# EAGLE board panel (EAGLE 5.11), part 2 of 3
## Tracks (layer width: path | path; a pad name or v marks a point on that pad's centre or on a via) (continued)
3.3V1  (via drill 0.4, 0.5) (continued)
  Top 0.406: SPEKTRUM_TX.3 150.02,10.82 151.45,12.25 151.45,14.71 v149.71,16.45
  Bottom 0.406: v159.07,21.26 | v159.07,21.26 | v159.07,21.26 | C96.1 145.26,24.33 IC31.5 C95.1 148.75,23.15 | 148.75,23.15 149.94,23.15 152.22,23.15 v152.64,22.72 154.23,21.14 157.25,21.14 158.79,21.14 v159.07,21.26 | v149.71,16.45 149.71,20.03 148.67,21.06 148.67,23.07 148.75,23.15 | v165.58,15.5 165.58,22.09 164.15,23.52 160.82,23.52 159.87,22.57 159.07,21.77 v159.07,21.26
3_3
  Top 0.254: JP4.3 86.96,35.55 86.96,28.06 87.52,27.5 87.81,27.5 89.06,26.25 IC12.48
5V
  Bottom 0.406: JP6.2 126.71,37.27 C79.1 126.69,39.04 | 126.69,39.04 IC27.5 | IC27.8 126.69,42.85 126.69,39.04
7.4V
  Bottom 0.406: 165.29,10.98 C88.1 163.52,10.95 163.44,10.95 163.44,11.21 | IC30.8 159.71,13.3 159.71,15.34 163.44,15.34 IC30.5 163.44,11.21 | VCC.1 161.37,6.61 161.77,7.01 161.77,10.42 162.56,11.21 163.44,11.21
!RE  (via drill 0.4)
  Top 0.406: 176.92,87.09 IC1.9 175.42,87.09 v175.01,87.5 | IC2.3 IC2.2 168.31,79.49 168.31,81.8 v168.71,82.2
  Bottom 0.406: v168.71,82.2 169.71,82.2 v175.01,87.5
!RE2
  Top 0.406: IC15.9 15.21,98.7 13.41,96.9 12.01,96.9 9.51,94.5 9.51,94.4 8.98,93.87 IC13.2 IC13.3
!RE3
  Top 0.305: OK8.6 31.75,22.24
  Top 0.406: 31.75,22.24 31.31,21.8 20.01,21.8 19.81,21.6 17.51,21.6 17.05,21.14 IC20.3 IC20.2
!RST  (via drill 0.4)
  Top 0.305: IC1.29 169.61,89.5 169.91,89.8 v170.31,89.8 | ISP.5 174.03,97.3 169.71,97.3 168.03,98.98 R1.1
  Bottom 0.305: v170.31,89.8 172.81,89.8 173.31,89.3 174.21,89.3 176.81,91.9 176.81,97.93 ISP.5
!RST1  (via drill 0.4)
  Top 0.305: IC15.29 17.61,106.01 17.91,105.7 v18.71,105.7 | v22.11,106.9 23.61,106.9 26.31,104.2 26.31,101.28 ISP1.5 27.79,99.88 29.01,101.1 31.61,101.1 32.63,102.12 R38.1
  Bottom 0.305: v18.71,105.7 22.11,105.7 v22.11,106.9
+3V1  (via drill 0.4)
  Top 0.254: 91.04,22 91.04,20.93 87.53,20.93 IC12.8 85.71,20.95 85.71,20.9 85.81,20.9 C40.2 | v90.41,21.9 90.51,22 91.04,22 | R30.2 85.41,25.05 v85.41,26.2 | R31.1 97.46,32.6 v100.21,32.6 | R32.2 104.56,23.55 103.91,24.2 v102.81,24.2 | 91.04,22 91.71,22.67 91.71,24.3 91.04,24.97 91.06,24.99 IC12.44 91.06,27.75 C41.2
  Top 0.406: JP4.9 101.86,35.41 C44.1 101.76,32.9 101.56,32.9 IC11.5 100.41,31.2 C43.1 100.31,32.5 v100.21,32.6
  Bottom 0.254: v102.81,24.2 102.81,25.2 100.81,27.2 100.81,32 v100.21,32.6
  Bottom 0.406: 87.01,26.1 88.31,24.8 88.31,24.2 89.61,22.9 90.31,22.9 90.41,22.8 v90.41,21.9 | 87.01,26.1 86.91,26.2 v85.41,26.2 | v100.21,32.6 91.51,32.6 87.81,28.9 87.81,26.9 87.01,26.1
+3V2  (via drill 0.4)
  Top 0.254: L5.P$1 L1A1.P$1
  Top 0.305: IC16.1 28.91,91.2 | v36.81,85.2 R43.2 | 28.91,91.8 v29.71,91.8
  Top 0.61: 28.91,90.5 28.91,91.2 28.91,91.8 28.91,94.3 L5.P$1
  Top 1.93: L5.P$1 28.76,96.05 30.01,97.3 C51.1 32.81,97.3 33.41,97.9 33.41,100.3 36.61,103.5 36.61,116.2 +5V1.MP
  Bottom 0.305: v36.81,85.2 35.61,86.4 35.61,88.5 33.11,91 30.61,91 29.81,91.8 v29.71,91.8
+5V  (via drill 0.4)
  Top 0.305: R1.2 168.05,101.55 ISP.2
  Top 0.406: 173.31,91.9 172.14,90.73 IC1.4 | 173.31,91.9 174.54,93.13 IC1.18 174.54,95.97 174.36,96.15 C3.1 | 173.31,91.9 173.74,91.47 v173.74,90.6 IC1.6 173.74,83.99 C2.1 172.6,82.09 172.21,81.7 171.41,81.7 170.91,81.2 170.91,75.4 | C12.2 177.36,77.4 IC4.1 175.92,76.01 175.31,75.4 170.91,75.4 | C1.1 169.55,71.09 IC2.8 169.55,74.94 170.01,75.4 170.91,75.4
  Bottom 0.406: v173.74,90.6 173.74,92.67 172.11,94.3 171.81,94.3 168.81,97.3 168.81,99.71 ISP.2
+5V1
  Bottom 0.406: IC29.8 C91.1 169.05,12.33 171.14,12.33 171.61,12.8 172.8,12.8 | IC29.8 | 172.8,12.8 IC29.5 | 172.8,12.8 | 172.8,12.8 175.74,12.8 176.46,12.09 176.46,9.31 175.82,8.67 173.92,8.67 SBUS.2 169.79,8.59 5V.1 | IC31.3 143.36,21.54 143.67,21.85 145.18,21.85 145.26,21.77 IC31.1 145.77,20.55 146.05,20.26 146.05,18.94 C94.1 146.13,18.86 146.13,17.8 147.96,15.9 148.83,15.02 | 155.02,16.93 155.26,17.17 156.14,18.04 156.65,18.56 C90.+ 158.81,18.76 IC30.1 IC30.2 160.9,19.71 160.5,20.1 160.5,21.85 160.9,22.25 C89.1 | 155.02,16.93 153.99,15.9 153.12,15.02 149.15,15.02 | 148.83,15.02 149.15,15.02 | 148.83,15.02 149.15,15.02 | 148.83,15.02 149.15,15.02 | IC29.8 166.47,14.73 166.06,14.31 165.18,14.31 164.79,14.71 164.47,15.02 164.47,16.06 164.23,16.29 163.68,16.29 158.36,16.29 155.66,16.29 155.02,16.93
+5V2  (via drill 0.4)
  Top 0.254: v100.91,25.9 100.91,28.6
  Top 0.406: 103.46,29.9 IC11.3 | 103.46,29.9 101.56,29.9 IC11.1 100.91,28.6 100.41,28.6 C42.1 | JP4.10 104.64,30.13 104.41,29.9 103.46,29.9
  Bottom 0.254: v100.91,25.9 100.91,25.8 99.91,24.8 99.31,24.8 98.81,24.3 U$1.VBUS
+5V3  (via drill 0.4, 0.6)
  Top 0.305: R38.2 31.84,104.96 ISP1.2
  Top 0.406: C47.1 10.75,103.78 10.75,103.22 12.09,101.87 IC15.6 v17.71,101.87 19.59,101.87 20.01,102.3 | 20.01,102.3 18.84,103.47 IC15.4 | 20.01,102.3 21.24,101.07 IC15.18 24.09,101.07 24.26,101.25 C49.1 | C63.2 13.91,85.2 IC17.1 v11.81,83.1 | IC13.8 14.47,95.14 C48.1 14.53,96.22 15.11,96.8 v16.21,96.8
  Bottom 0.406: ISP1.2 28.42,106.8 24.81,106.8 22.41,104.4 22.41,103.5 20.79,101.87 v17.71,101.87 16.21,100.37 v16.21,96.8 16.21,94 12.81,90.6 12.81,85.9 11.81,84.9 v11.81,83.1
+5V4  (via drill 0.4)
  Top 0.305: OK7.8 93.56,48.45 94.11,49 C57.2 96.01,49.8 96.01,52.1 | 103.11,52.5 102.99,52.63 IC14.4 97.74,52.63 97.21,52.1 96.01,52.1 | 96.01,52.1 93.69,52.1 OK6.2
  Top 0.35: IC14.20 104.59,49.38 103.12,47.91 103.11,47.92 103.11,52.5 103.11,54.8 | R45.2 R46.2 116.73,55.08 116.11,55.7 104.01,55.7 103.11,54.8 | 103.11,54.8 103.12,54.79 | L6.2 105.07,43.35 | 98.46,44.7 R47.1
  Top 0.406: 105.14,43.27 L6.2 104.41,43.17 | 104.41,43.17 104.36,43.17 C54.1 | 103.12,47.91 103.12,45.09 103.81,44.4 103.81,43.3 | 103.81,43.3 103.81,43.2 104.38,43.2 104.41,43.17 | 103.81,43.3 102.66,43.3 C56.+ 100.25,42.36 v99.51,43.1 99.51,43.65 98.46,44.7
  Bottom 0.35: 93.71,41.8 94.61,40.9 97.31,40.9 v99.51,43.1
+5V5
  Top 0.406: 30.01,26.8 30.01,27.1 | 6.71,19.2 IC18.1 6.71,20.8 | 28.61,25.5 C72.1 | 36.56,25.6 36.58,25.59 | 14.51,23.3 14.41,23.2 14.11,22.9
  Top 0.61: OK4.8 OK4.7 36.58,25.59 | OK8.8 OK8.7 30.48,24.54 30.01,25 30.01,25.5 | 30.01,27.1 29.31,27.7 21.81,27.7 arc90 R63.1 20.81,27.6 20.31,27.1 20.31,24.5 19.01,23.2 14.41,23.2 | 30.01,25.5 30.01,26.8 33.01,26.8 C71.1 36.56,25.6 | 30.01,25.5 28.61,25.5
  Top 0.813: 14.51,23.3 IC20.8 | 14.11,22.9 C73.1 7.41,22.9 6.71,22.2 6.71,20.8 C65.2
+5V6  (via drill 0.4)
  Top 0.305: 126.11,15.3 126.11,14.75 126.38,14.48 IC32.6 131.18,14.48 v132.06,15.1 | 126.11,15.3 126.11,15.8 126.39,16.08 IC32.4 | C97.2 126.11,15.3 | R89.2 v128.81,23.1 129.14,23.38 R90.1 R93.1 | R92.1 R91.1 141.16,23.39 141.16,22.55 140.76,22.15 v139.76,22.15 | SG4.- 139.59,11.91 L15.1 139.62,13.7 C102.2
  Bottom 0.305: 139.46,7.3 134.71,7.3 133.39,8.58 132.06,9.9 v132.06,15.1 132.06,19.2 129.96,21.3 129.96,21.95 129.41,22.5 | 139.58,7.3 ISP2.2 | 139.58,7.3 139.61,7.22 | IC33.1 124.11,21.03 C101.2 124.11,23.5 125.11,24.5 127.41,24.5 v128.81,23.1 129.41,22.5 | 129.41,22.5 129.81,22.9 132.66,22.9 133.36,22.2 139.71,22.2 v139.76,22.15 | 139.46,7.3 139.58,7.3 | 139.46,7.3 139.46,10.44 SG4.-
+12V  (via drill 0.4, 1)
  Top 0.406: IC6.7 159.09,60.33 158.26,61.15 Q8.2 | IC7.7 159.29,75.12 158.26,76.15 Q9.2 | IC8.7 158.99,91.73 157.96,92.75 Q10.2 | IC3.7 158.39,107.62 157.96,108.05 Q7.2 | R17.2 161.51,95.5 v160.61,96.4 | R14.2 161.71,78.6 v160.61,79.7 | v160.61,63.5 R11.2 | IC4.8 C13.2 v177.51,71
  Top 0.61: R8.2 159.31,112 159.11,112
  Top 1.27: C8.1 v160.61,63.5 Q8.2 | C10.1 160.61,81.9 v160.61,79.7 158.36,79.7 Q9.2 | C14.1 v160.61,96.4 158.06,96.4 Q10.2 | 160.31,112.9 C6.1 | 160.31,112.9 159.41,112 159.11,112 Q7.2 | 160.31,112.9 159.91,113.3 v159.81,113.3
  Top 1.778: X2.4 X2.5 | X1.5 X1.4
  Bottom 0.406: v177.51,71 175.66,72.85 175.66,74.05
  Bottom 1.27: v159.81,113.3 162.86,110.15 162.86,109.35
  Bottom 1.93: v160.61,63.5 v160.61,79.7 v160.61,96.4 160.61,107.1 162.86,109.35 164.51,111 171.42,111
  Bottom 2.54: X2.4 171.41,69.8 175.66,74.05 179.01,77.4 179.01,111 171.42,111 X1.5
+12V1  (via drill 0.6)
  Top 0.3: IC16.4 27.81,88.8 27.81,88.5
  Top 0.406: v10.71,75.4 10.41,75.4 5.61,80.2 5.61,84.2 IC17.8 4.22,85.2 C62.2
  Top 0.813: 27.81,88.5 27.81,87.5 28.91,86.4 C60.1
  Top 1.016: 29.11,76.09 29.21,76.2 31.01,78 31.01,80.1 28.91,82.2 C60.1 C59.1 | C61.1 22.99,74.83 X11.4
  Top 1.27: X11.5 29.21,76.2
  Top 1.778: X13.5 X13.4
  Top 1.93: X11.5 25.91,74.8 X11.5
  Top 2.184: X13.4 X11.4
  Bottom 0.406: v10.71,75.4 11.03,75.08 X13.5
  Bottom 1.778: X11.4 X11.5 | X13.5 X13.4
+12V2  (via drill 0.4)
  Top 0.305: v123.16,19.4 123.16,22.05 125.76,24.65 v128.81,24.65
  Bottom 0.305: v123.16,19.4 124.25,18.32 IC33.8 124.22,15.67 C100.2 124.21,12 123.8,11.59 SV2.4 | v128.81,24.65 128.96,24.5 140.26,24.5 140.96,23.8 140.96,21.35 140.91,21.35 140.66,21.1 138.55,21.1 R95.2
+18V  (via drill 0.6)
  Top 0.305: v138.17,108.54 138.96,109.18 139.11,109.33 IC21.7 139.13,111.71 R66.2 | R69.2 139.13,83.77 IC22.7 139.13,81.24 138.49,80.6 v138.33,80.62 | R72.2 139.13,93.14 IC23.7 139.12,90.76 138.33,89.97 v138.17,89.97 | R78.2 139.13,74.56 IC25.7 139.13,72.2 138.33,71.4 v138.33,71.24 | R75.2 139.13,102.34 IC24.7 139.13,100.45 138.17,99.5 v138.17,99.18
  Top 1.27: v138.17,108.54 135.79,108.54 C16.1 135,107.94 Q11.2 | v138.17,99.18 135.79,99.18 C24.1 135,98.57 Q14.2 | v138.17,89.97 135.95,89.97 C21.1 135,89.37 Q13.2 | v138.33,80.62 136.24,80.62 C19.1 135,80 Q12.2 | v138.33,71.24 136.08,71.24 C74.1 135,70.79 Q15.2
  Bottom 1.27: P+18T2.1 140.87,118.74 140.87,108.54 | 140.87,99.18 140.87,108.54 | v138.17,108.54 140.87,108.54 | 140.87,99.18 v138.17,99.18 | 140.87,89.97 v138.17,89.97 | 140.87,89.97 140.87,99.18 | 140.87,80.62 140.87,89.97 | 140.87,71.24 140.87,80.62 | 140.87,80.62 v138.33,80.62 | v138.33,71.24 140.87,71.24 | 140.87,71.24 140.87,65.81 JP1T2.7
  pour Bottom (no thermals): 138.49,66.16 138.49,62.67 142.3,62.67 142.3,120.77 139.44,120.77 139.44,116.32 140.23,116.32 140.23,113.31 138.8,109.5 138.8,71.55 138.96,70.76 139.28,70.44 139.28,66.95
+18V1  (via drill 0.4, 0.6, 1)
  Top 0.305: 62.46,31.62 PAD2.1 | 69.69,34.95 XL.4 | +18_L.1
  Top 0.406: +18_R.1 65.16,117.66 v65.16,116.07 | XL.4 XL.5 | XR.5 69.71,102.26 | v65.32,24.95 +18_L.1 65.8,22.09 | 70.88,34 70.72,34.63
  Top 0.61: 79.45,40.03 79.45,51.16 IC10.8 | C32.1 79.34,39.92 79.45,40.03 | JP1.7 62.71,96.14 62.62,96.06 | v63.73,30.43 62.46,31.62 | 62.62,90.65 arc-90 C37.+ | v70.56,28.12 76.27,28.12 76.27,30.51 79.45,30.51 79.45,40.03
  Top 1.778: 62.62,90.65 62.62,92.81 v61.99,93.45 62.71,94.17 JP1.7
  Bottom 0.305: 61.99,30.03 62.79,30.82 | 65.8,25.9 65.8,25.11 65.96,24.95 v65.32,24.95 65.8,26.06 65.8,25.9 | 65.8,25.9 65.32,25.43 | v70.72,34.47 69.92,34.95 70.4,34.95 70.4,34.47
  Bottom 0.406: 61.51,63.05 61.51,63.84 61.99,63.84 | 62.62,94.24 61.99,94.64 61.99,98.45
  Bottom 0.61: 62.79,30.82 63.18,30.43 v63.73,30.43 | 62.62,94.24 61.99,93.61 v61.99,93.45 | 69.21,29.31 v70.56,28.12
  Bottom 2.311: v70.72,34.47 70.4,34.47 70.4,30.51 69.21,29.31 65.32,25.43 61.99,28.75 61.99,30.03 61.99,63.84 61.99,98.45 61.99,111.63 65.16,114.8 v65.16,116.07 65.16,113.85 70.24,108.77 70.24,105.28 69.69,104.72 v69.69,98.05
  pour Top (no thermals): 69.45,103.37 71.19,103.37 71.19,98.77 70.24,97.18 69.13,97.18 68.75,98.13 69.45,99.4
  pour Top (no thermals): 69.62,33.6 69.62,34.17 69.61,34.79 69.61,38.6 69.77,38.76 70.88,38.76 70.88,35.74 71.19,35.73 71.69,34.91 71.91,34.53 71.41,33.54 69.98,33.54
+18V2
  Top 1.93: D11.A 18.41,60.88 +1.MP
+18V_PI1
  Top 1.8: X15.4 X15.5
  Top 1.93: X14.4 X14.5 | D11.C 21.75,54.24 21.81,54.3
  Top 2.184: X14.4 18.58,55.54 19.81,54.3 21.81,54.3 25.79,54.3 X15.4
+24V1
  Top 0.406: 14.2,33.3 X16.5 13.7,32.8 7.81,32.8 5.51,30.5 5.51,25.1 5.81,24.8 | IC18.8 6.51,24.51
  Top 0.813: IC18.8 5.81,24.8 5.21,24.8 C64.2
  Top 1.93: X16.4 X16.5 | X17.5 X17.4
  Top 2.184: X17.4 22.15,33.57 20.88,34.84 X16.4
+24V_SB
  Top 1.676: X8.4 49.68,20.77 50.95,22.04 50.95,23.94
  Top 2.05: X8.4 X8.5 | X9.5 X9.4
  Top 2.54: X9.5 49.68,112.47 50.41,113.2 57.81,113.2 58.61,112.4 58.61,102.3 55.01,98.7 C23.+ C26.+ C27.+ C28.+ C29.+ C30.+ 50.95,23.94
  pour Top (isolate 0.406): 40.11,120.7 60.61,120.7 60.61,5.2 40.11,5.2
+USB_SIEVED1  (via drill 0.4)
  Top 0.305: 10.29,9.12 IC19.20 12.79,9.12 13.11,8.8
  Top 0.406: 10.29,9.12 v10.21,9.2 | v7.01,12.2 6.84,12.38 IC19.4 | 18.61,7.4 R60.1 18.51,8.1 | 13.11,8.8 16.21,8.8 16.31,8.7 C67.1 16.51,8.1 18.51,8.1 | OK5.8 OK5.7 25.75,15.44 25.11,14.8 R62.1 R61.1 25,12.2 L7.2 23.31,9.9 C69.+ | C70.2 22.91,12.3 C69.+ | R58.1 21.71,11.5 C69.+ | R58.1 R59.1 | 18.51,8.1 18.51,8.8 19.41,9.7 R58.1
  Bottom 0.406: v10.21,9.2 10.01,9.2 v7.01,12.2
_VCC
  Top 0.813: JP2T.2 94.2,116.23 93.25,117.19 P+5T.1
_VCC1
  Top 0.813: JP2T1.2 115.9,116.23 114.95,117.19 P+5T1.1
_VCC2
  Top 1.016: JP2T2.2 135.95,116.32 134.99,117.28 P+5T2.1
A  (via drill 0.4)
  Top 0.406: X1.3 173.96,108.86 172.11,110.7 168.41,110.7 165.11,107.4 v165.11,101.7 | IC2.6 167.01,72 166.21,71.2 v165.51,71.2
  Bottom 0.406: v165.11,101.7 164.71,101.3 164.71,71.2 | X2.3 170.15,63.84 169.11,62.8 166.01,62.8 164.71,64.1 164.71,71.2 | 164.71,71.2 v165.51,71.2
A1_1
  Bottom 0.406: X9.3 52.22,106.31 45.61,99.7 45.61,24 48.41,21.21 X8.3
A2  (via drill 0.4)
  Top 0.406: IC13.6 14.41,92.6 14.61,92.4 14.61,90.4 v14.11,89.9 | X13.3 12.51,79.56 12.51,82 v13.71,83.2
  Top 0.61: X11.3 28.46,73.56 30.21,71.8 30.21,70.3 29.31,69.4 14.91,69.4 12.51,71.8 12.51,75.68 X13.3
  Bottom 0.406: v14.11,89.9 14.11,83.6 v13.71,83.2
A3  (via drill 0.4)
  Top 0.406: v17.21,28.1 17.05,27.94 IC20.6 | v10.81,34.4 12.52,36.11 X16.3
  Bottom 0.406: X17.3 25.01,32.3 20.81,28.1 v17.21,28.1 13.31,28.1 10.81,30.6 v10.81,34.4
A_PI1
  Bottom 0.406: X15.3 30.86,53.55 29.81,54.6 29.81,54.7 29.01,55.5 26.61,55.5 23.11,59 17.01,59 14.61,61.3 10.81,61.3 9.91,60.3 9.91,57.5 10.61,56.81 X14.3
ADC0  (via drill 0.4)
  Top 0.305: PC0.1 63.1,69.88 | 63.1,69.88 | PC0.1 62.94,69.72 | PC0.1 62.15,69.88 63.1,70.83 63.57,70.83 64.11,71.37 IC5.23 67.29,71.37 67.94,72.02 v67.94,72.26 | v66.03,109.64 66.08,109.64 SW1.1
  Bottom 0.305: v67.94,72.26 67.38,72.81 67.38,75.43 68.02,76.07 68.02,79.72 65.24,82.5 65.24,108.85 v66.03,109.64
ADC1  (via drill 0.4, 0.4 pad 0.01)
  Top 0.305: PC1.1 62.3,67.34 62.62,67.34 62.62,67.41 63.42,68.37 65.48,68.37 65.48,70.57 IC5.24 67.68,70.57 v67.7,70.59 | SW1.6 73.84,113.37 72.15,113.37 70.88,112.1 68.97,112.1 68.65,112.42 67.38,112.42 64.84,109.88 v64.84,109.72
  Bottom 0.305: v67.7,70.59 67.38,70.91 67.38,71.46 66.75,72.1 66.75,75.59 67.38,76.23 67.38,79.48 64.61,82.26 64.61,109.48 v64.84,109.72
ADC2  (via drill 0.4)
  Top 0.305: IC5.25 67.92,69.4 v66.99,69.4 66.11,69.4 66.11,67.73 65.48,67.73 65.48,66.22 64.05,64.8 PC2.1 | SW1.4 71.04,114.59 71.04,113.77 70.08,112.82 69.21,112.82 68.65,113.37 66.43,113.37 65,111.94 v65,111.31
  Bottom 0.305: v66.99,69.4 66.75,69.64 66.75,70.99 66.11,71.62 66.11,75.91 66.75,76.54 66.75,79.08 63.97,81.86 63.97,110.28 v65,111.31
ADR_DEC
  Top 0.305: SJ7.1 SJ6.1 | 61.72,82.56 61.86,82.42 63.1,82.42 64.37,81.31 65.16,81.31 66.91,79.56 70.4,79.56 71.12,78.84 IC5.12 71.19,77.58 | SJ1.1 73.97,83.87 SJ2.1 SJ3.1 SJ4.1 SJ5.1 SJ6.1 | SJ6.1
  Top 0.406: PB0.1 61.72,82.56 61.67,82.58 SJ7.1
B  (via drill 0.4)
  Top 0.406: v166.81,68.8 171.94,68.8 X2.6 | IC2.7 168.28,75.93 v167.11,77.1
  Bottom 0.406: 165.61,77.4 165.61,100.7 166.21,101.3 166.21,102.3 169.65,105.74 X1.6 | v167.11,77.1 165.91,77.1 165.61,77.4 | v166.81,68.8 166.81,72.1 165.61,73.3 165.61,77.4
B1
  Top 1.016: JP2T2.3 133.41,116.17 132.14,117.43 PB1T2.1
B1_1  (via drill 0.6)
  Top 0.406: v42.71,13.3 43.21,12.8 51.41,12.8 v52.22,13.61
  Bottom 0.406: v42.71,13.3 42.71,101.4 48.41,107.09 X9.6 | X8.6 v52.22,13.61
B2
  Top 0.813: PB1T.1 91.19,118.33 91.19,114.9 JP2T.3
B3
  Top 0.813: PB1T1.1 112.89,118.33 112.89,114.9 JP2T1.3
B4  (via drill 0.7)
  Top 0.406: IC13.7 14.84,93.87 15.51,93.2 15.51,83.7 v18.81,80.4
  Top 0.61: X11.6 21.85,77.37 v18.81,80.4
  Bottom 0.61: v18.81,80.4 18.81,74.9 17.72,73.81 X13.6
B5
  Top 0.406: X16.6 17,31.79 15.41,30.2 15.41,28.5 15.78,28.14 IC20.7
  Bottom 0.406: X16.6 20.61,32.3 24.42,36.11 X17.6
B_PI1
  Bottom 0.406: X14.6 10.22,53 9.11,54.1 9.11,61 10.41,62.4 15.01,62.4 17.61,59.7 23.41,59.7 26.31,56.81 X15.6
C3/ADC1
  Top 0.813: JP2T1.6 105.74,116.08 103.52,118.3 PC3T1.1
C3/ADC2
  Top 1.016: JP2T2.6 125.79,115.37 123.56,117.59 PC3T2.1
C3/ADC3
  Top 0.813: JP2T.6 84.04,116.08 81.82,118.3 PC3T.1
C4/ADC4/SDA
  Top 0.813: JP2T.5 86.58,116.08 84.68,117.98 PC4T.1
C4/ADC4/SDA1
  Top 0.813: JP2T1.5 108.28,116.08 106.38,117.98 PC4T1.1
C4/ADC4/SDA2
  Top 1.016: JP2T2.5 128.33,115.69 126.42,117.59 PC4T2.1
C5/ADC5/SCL
  Top 0.813: JP2T.4 89.12,117.22 PC5T.1
C5/ADC5/SCL1
  Top 0.813: JP2T1.4 110.82,117.22 PC5T1.1
C5/ADC5/SCL2
  Top 1.016: JP2T2.4 130.87,116.01 129.28,117.59 PC5T2.1
CTS_E
  Top 0.3: 158.98,46.13 161.07,44.04 U$3.10
  Top 0.305: SV1.2 158.98,46.13
CTS_S
  Top 0.3: U$3.18 158,38.59 157.61,38.2
  Top 0.305: 157.61,38.2 148.71,38.2 147.23,36.72 X4.8
DCD_S
  Top 0.3: 162.57,32.86 U$3.24
  Top 0.305: 162.57,32.86 161.91,32.2 155.88,32.2 X4.1
DSR_E
  Top 0.3: 154.61,42.6 156.62,40.59 U$3.14
  Top 0.305: SV1.6 149.42,44.89 151.71,42.6 154.61,42.6
DSR_S  (via drill 0.4)
  Top 0.3: U$3.22 161.57,35.16 v159.71,33.3
  Bottom 0.305: v159.71,33.3 158.51,34.5 151.04,34.5 X4.6
DTR_E
  Top 0.3: 152.92,40.09 U$3.15
  Top 0.305: SV1.8 152.92,40.09
DTR_S  (via drill 0.4)
  Top 0.3: U$3.23 162.07,34.06 v161.41,33.4
  Bottom 0.305: v161.41,33.4 157.71,37.1 153.64,37.1 X4.4
GND  (via drill 0.4, 0.7)  (1 unrouted)
  Top 0.305: 172.14,94.23 172.14,96.19 | IC1.21 172.14,92.23 171.31,91.4 171.34,91.37 IC1.3
  Top 0.406: IC1.5 172.94,84.33 172.66,84.05 171.78,84.05 171.34,84.49 IC1.3 | IC6.5 161.34,59.03 v162.17,59.15 | IC3.5 158.14,106.33 v157.61,105.8 | IC8.5 158.34,90.43 v157.91,90 | IC7.5 158.94,73.83 v158.31,73.2
  Top 0.61: 174.51,105.2 arc284 174.51,106.3 175.04,105.77 X1.2 | 175.81,108.9 arc-293 175.71,107.9 176.12,108.31 X1.1 | 168.41,63.8 arc-307 168.41,64.6 168.05,64.24 X2.1 | 169.61,67.3 arc293 169.71,66.3 169.23,66.78 X2.2
  Bottom 0.406: v157.61,105.8 157.61,103.5 v157.27,102.94 | v157.91,90 157.91,86.91 v158.37,86.45 | v158.31,73.2 158.31,70.41 v158.37,70.35
  Bottom 0.61: 168.41,64.6 arc180 166.81,63.9 167.15,64.24 X2.1 | 169.31,67.6 arc242 169.41,66.1 168.88,66.64 X2.2 | 174.41,106.2 arc-307 174.41,105.4 174.86,105.4 X1.2 | 176.91,107.5 arc-100 175.71,108 176.19,108 X1.1
  other vias: 147.42,109.96 172.27,56.85 170.92,91.96 170.35,117.5 174.09,115.5 162.65,115.84 158.32,102.15 158.2,100.86 172.21,55.45 175.37,54.68 168.77,113 170.62,58.66 173.41,117.35 173.92,56.55 170.28,56.62 171.71,116.25 173.88,58.49 172.62,114.05 170.01,115.65 170.59,113.64 158.27,85.25 158.27,84.05 158.27,67.85 158.27,69.15 152.77,69.25 151.17,69.25 149.57,69.45 147.97,69.65 153.57,53.45 149.67,53.85 148.07,53.75 146.17,53.95 153.27,102.25 151.57,102.05 149.77,102.05 148.17,102.55 153.37,85.65 151.87,85.65 149.97,85.95 148.37,86.25 151.27,67.65 149.67,68.15 151.67,84.25 150.17,84.55 151.67,100.45 150.17,100.65 168.07,117.05 153.77,117.35 174.37,68.95 175.57,69.75 166.87,75.45 168.37,95.65 170.97,74.15 168.27,94.25 172.37,80.25 147.22,93.86 147.32,77.06 147.22,60.76 156.77,57.75 165.87,54.35
  pour Bottom (isolate 0.305, rank 2): 142.13,52.34 180.91,52.4 180.91,120.19 142.13,120.18
  pour Top (isolate 0.406, rank 2): 142.16,52.32 180.91,52.3 180.91,120.12 142.13,120.18
GND1  (via drill 0.4, 0.6, 1)
  Top 0.305: IC5.21 65.08,72.97 64.45,72.97 63.97,73.45 61.64,73.45 61.25,73.84 C36.1 C35.1 | 69.77,57.33 69.77,55.59 v70.64,54.95 | SW1.TAB2 73.73,109.09 | XL.1 XL.2 67.23,38.7 67.23,35.27 67.54,34.95 | 67.54,34.95 v67.38,34.16 | 67.07,34.16 67.07,34.47 67.54,34.95 | 67.94,34.16 67.78,34.08 67.38,33.68 | JP3A.6 v74.37,30.66 | JP3A.6
  Top 0.406: GND_R.1 62.46,117.02 | IC9.5 75,59.72 v74.05,59.72 | v74.05,59.72 v74.05,60.83 | 69.77,57.33 JP3B.6 | R27.2 73.21,59.72 v74.05,59.72 | IC5.21 67.3,72.97 67.86,73.53 69.84,73.53 71.67,71.7 v72.37,71.7 73.65,71.7 74.12,72.17 IC5.3 | 76.03,73.77 IC5.5 v73.42,73.77 | 79.45,72.89 79.45,73.95 C31.1 C18.1 | 76.03,73.77 | 76.03,73.77 76.91,72.89 79.45,72.89 | 79.45,72.89 79.45,71.36 C34.2
  Top 0.61: 72.94,31.46 JP3A.6 72.78,30.35 | 62.15,23.52 62.15,24 62.38,23.76 62.15,23.52 | GND_L.1 62.15,23.52 | 62.15,23.52 | 76.59,43.05 76.59,44.3 JP2.1 77.09,44.79 v77.86,44.79 | C32.2 v77.86,43.21 | v77.86,43.21 | v77.86,43.21 v77.86,44.79 | v77.86,44.79 | v77.86,44.79 77.86,48.44 | 77.86,48.44 77.86,49.71 77.54,50.03 IC10.7 IC10.6 76.27,50.03 75.64,49.4 v75.48,49.4 | 77.86,48.44 C33.2 | IC10.2 IC10.3 76.27,54.32 arc-90 v76.12,54.16 | v76.12,54.16 v77.39,54.16 | v75,54.16 v76.12,54.16 | PAD1.1 PAD5.1 65.88,39.24 XL.1 | 71.51,91.78
  Top 0.813: 74.43,102.58 73.84,102.58 XR.2 | 74.43,102.58 v76.27,102.58 77.54,102.58 77.95,102.18 JP1.1 | 74.43,102.58 XR.1
  Top 1.422: v72.31,91.31 71.67,91.31 70.4,91.31 69.61,90.51 C37.-
  other vias: 61.83,25.03 61.83,116.07 70.24,117.5 73.58,112.26 77.86,46.38 73.42,63.84 68.97,42.89 73.73,79.56
  pour Bottom (isolate 0.305): 80.4,20.34 80.4,120.68 60.24,120.68 60.24,20.34
  pour Top (isolate 0.305, rank 2): 60.24,120.68 80.4,120.68 80.4,20.34 60.24,20.34
  pour Top (no thermals): 76.91,100.36 73.73,100.36 73.73,104.8 76.91,104.8
  pour Top (no thermals): 65.8,38.76 65.8,35.27 66.75,34.47 67.07,33.52 67.86,33.52 68.18,33.84 68.18,34.32 67.86,34.63 67.86,35.27 67.38,35.74 67.38,38.76
GND2  (via drill 0.5)
  Top 0.254: 92.81,28 92.56,27.75 IC12.41 92.56,24.6 | IC12.5 85.06,22.45 83.61,23.9
  other vias: 90.11,19.95 81.46,15.95 87.01,17.9 102.91,19.6 105.01,20.8 102.21,27.1 99.01,29.8 97.71,29.7 97.31,28.5 81.96,28.55 81.56,24.55 93.56,29.25 93.96,31.25 92.76,23.65 91.16,19.25 105.11,24.3
  pour Top (isolate 0.305): 80.26,10.9 106.26,10.9 106.26,37.65 80.26,37.65
  pour Bottom (isolate 0.305): 80.26,10.9 106.26,10.9 106.26,37.65 80.26,37.65
GND3  (via drill 0.7, 1)
  Top 0.254: 31.82,88.3 IC16.6 33.11,87.6
  Top 0.305: R42.2 T4.3 | T3.3 11.66,110.15 R40.2 | IC15.21 20.34,103.47 19.51,104.3 19.49,104.27 IC15.3 | T3.1 11.8,107.65 R39.2 | 31.01,88.4 33.11,87.6
  Top 0.406: IC15.5 12.44,102.67 12.16,102.95 12.16,103.84 12.6,104.27 IC15.3 | C62.1 4.75,86.47 IC17.7 | IC17.2 14.08,86.47 C63.1 | C49.2 24.2,103.47 IC15.21 | 30.41,90.6 30.61,90.6 31.01,91 | 32.61,94.9 32.91,94.6 32.91,93.4 32.41,93.4 C51.2
  Top 0.61: 31.41,91.1 31.61,89.9 31.61,88.1 | 31.01,88.4 IC16.PAD 31.01,91 31.01,91.1 | 30.41,90.6 30.41,88.6 | 32.41,93.4 30.71,93.4 | 32.61,94.9 30.91,94.9
  Top 0.813: 26.91,111.8 28.31,111.8 | 28.61,109.1 28.41,108.9 28.41,108.8 27.01,108.8 | 10.31,110.1 11.71,110.1 | 10.61,107.3 11.61,107.6
  Bottom 0.61: 13.61,80.1 arc353 13.61,80.2 14.41,80.2 X13.1 | 16.11,79 arc-354 16.11,78.9 | 27.51,71 arc-354 27.51,70.9 | X11.2 25.5,71.9 25.41,71.6 arc340 25.21,71.8
  other vias: 24.31,112.81 29.85,112.58 29.91,108.05 29.2,110.88 30.1,109.51 28.67,109.2 25.77,98.1 34.06,94.84 20.37,104.2 38.22,95.16 36.11,95.52 8.35,108.88 9.14,109.9 9.63,108.76 9.17,107.5 31.46,92.64 7,104.81 7.35,103.48 32.36,84.09 32.07,86.71 7.58,97.9 33.35,86.84 4.07,95.2 3.7,91.06 30.99,89.32 4.66,90.3 10.4,91.34 9.26,89.3 9.17,87.2 21.36,89.5 17.8,91.44 9.16,84.9 25.81,87.94 18.67,90.1 17.36,87.51 26.36,82.69 26.13,86.73 17.46,84.11 23.1,84.63 30.36,75.01 30.36,73.81 22.86,82.59 19.16,82.71 21.05,80.22 24.3,78.78 10.65,73.32 9.15,74.02 10.85,78.02 10.65,79.42 12.75,69.12 10.75,71.72 33.35,78.62 35.25,72.62
  pour Bottom (isolate 0.559, rank 2): 0.75,120.18 0.31,66.4 41.2,66.4 41.29,120.08
  pour Top (isolate 0.559, rank 2): 0.63,120.25 0.41,66.4 41.43,66.4 41.29,120.18
GND4  (via drill 0.5)
  Top 0.305: 116.11,44.1 116.61,44.1 | 116.61,44.1 116.61,43.5 | 117.51,48 116.61,48 116.61,44.1
  Top 0.35: IC14.26 104.29,53.28 104.11,53.1 104.11,52.3 | 104.11,52.3 104.11,50.3 104.39,50.03 IC14.21 107.49,50.03 107.71,49.8 | IC14.25 104.44,52.63 104.11,52.3 | 107.71,49.8 107.71,48.2 107.59,48.08 IC14.18 | 107.71,49.8 108.54,49.8 C55.2 108.17,49.74 | 108.15,41.44 C53.2 110.15,41.44 110.51,41.8 | 116.11,44.1 116.11,46.2 | v101.01,50.7 100.99,50.68 IC14.7 97.47,50.68
  Top 0.813: 118.41,43.5 116.61,43.5 116.41,43.5
  other vias: 110.01,51 108.01,49.1 104.61,52.2 101.11,46.7 99.21,40.8 110.31,40.8 110.61,43.1 115.01,46.3
  pour Top (isolate 0.4): 119.51,56.7 92.55,56.7 92.55,39.5 119.51,39.5
  pour Bottom (isolate 0.406): 92.63,39.5 119.51,39.5 119.51,56.7 92.63,56.7
GND5  (via drill 0.5)
  Top 0.254: C77.1 124.41,46.21 124.41,40.39 126,38.8 129.54,38.8 C78.1 | IC26.5 132.59,43.16 132.59,44.76 IC26.3 131.24,44.81 131.24,44.84 | 131.24,44.84 131.4,44.84 | 131.24,44.84 130.1,44.84
  Top 0.406: JP6.1 124.17,35.39
  other vias: 125.52,47.37 138.22,43.33 138.22,45.07 139.89,48.33 132.83,51.5 137.83,51.98 125.45,39.04 129.97,37.45 139.26,31.5 132.86,46.28
  pour Bottom (isolate 0.508): 123.06,56.42 140.84,56.42 140.84,27.69 123.06,27.69
  pour Top (isolate 0.508): 122.9,56.42 140.68,56.42 140.68,27.69 122.9,27.69
GND6  (via drill 0.5)
  Top 0.3: U$3.2 164.32,39.09 164.61,38.8
  Top 0.305: 164.61,38.8 164.61,37.2
  other vias: 146.46,40.39 143.51,43.53 175.13,48.44 168.01,48.85 170.53,44.06 164.83,32.8 175.84,32.8 176.68,35.49 167.62,32.5 179.59,32.81 179.23,48.26 143.75,37.35
  pour Bottom (isolate 0.406): 182.18,30.52 182.28,50.52 142.24,50.62 142.24,30.67 142.28,30.67
  pour Top (isolate 0.406): 182.18,30.52 182.28,50.52 142.24,50.62 142.24,30.67 142.28,30.67
GND7  (via drill 0.5)
  Top 0.254: IC28.5 159.39,16.85 157.79,16.85 IC28.3 157.75,15.5 157.71,15.5 | 157.71,15.5 157.71,15.66 | 157.71,15.5 157.71,14.36 | 158.59,22.93 158.59,23.99 158.59,24.23
  Top 0.406: SBUS.1 172.8,6.06 | v161.61,20.66 161.61,21.93 161.06,22.49 159.23,22.49 v157.96,22.57 | IC28.21 158.59,24 158.59,23.99
  Bottom 0.406: C94.2 144.28,20.52 IC31.2 | IC30.3 162.17,20.66 v161.61,20.66 | C95.2 147.8,20.47 v147.8,19.71
  other vias: 155.18,9.79 156.45,22.57 154.23,24.15 151.69,16.53 150.02,21.61 164.31,9.07 167.17,10.58 173.68,24.39 147.8,18.52 148.36,25.5 150.74,25.5 144.71,14.79 144.47,27.33 153.44,12.96 164.23,27.01 174.47,19.23 175.82,15.26 171.53,16.69 167.01,12.8 170.58,10.02 157.88,8.75
  pour Bottom (isolate 0.508): 142.09,4.15 142.01,28.92 181.06,28.92 181.14,4.15
  pour Top (isolate 0.508): 142.01,4.15 142.01,28.99 180.98,28.76 180.98,3.91
GND8  (via drill 0.4)
  Top 0.305: 129.11,15.28 IC32.5 | 129.11,15.28 130.54,15.28 131.34,16.08 v134.26,16.08 IC32.21 137.54,16.08 C99.1 | 129.11,15.28 129.11,16.5 128.73,16.88 IC32.3 124.89,16.88 124.06,16.05 C97.1 | C98.1 136.91,11 v136.61,11.3
  Bottom 0.305: IC33.2 IC33.3 | IC33.7 IC33.6 | IC33.7 125.52,13.72 C100.1 126.02,12.19 131.42,6.79 SV2.1 131.69,6.03 ISP2.6 | IC33.7 IC33.2 | IC33.2 125.41,21 C101.1 | 136.71,15.54 134.8,15.54 v134.26,16.08 | 136.71,15.54 R94.2 | v136.61,11.3 136.61,15.44 136.71,15.54
  other vias: 129.76,16.1 129.36,13.3 125.66,18.3 127.11,23.1 134.36,17.95 129.01,9.4 138.81,17.6 123.16,17.55 123.06,12.35
  pour Bottom (isolate 0.254): 122.11,4.05 142.11,4.05 142.11,25.9 122.11,25.9
  pour Top (isolate 0.254): 122.11,4.05 142.11,4.05 142.11,25.9 122.11,25.9
GND9  (via drill 0.5)
  Top 0.406: IC34.4 75.51,13.65 v75.51,15.65 | C103.1 68.01,15.45 v68.01,15.9
  Bottom 0.406: v75.51,15.65 75.51,15.9 v68.01,15.9
  other vias: 69.76,8.65
  pour Top (isolate 0.305): 60.26,4.15 80.26,4.15 80.26,18.65 60.26,18.65
  pour Bottom (isolate 0.305): 60.26,4.15 80.26,4.15 80.26,18.65 60.26,18.65
GND_AL1  (via drill 0.4)
  Top 0.406: v9.21,21.7 9.21,19.64 IC18.3 IC18.2 | IC18.7 IC18.6 | v4.41,27.1 4.51,27 | 26.71,25.9 C72.2 | 33.14,23.4 OK8.5 | 32.81,25.5 C71.2 | OK4.5 39.12,25.31 v39.41,25.6
  Top 0.61: v27.61,26.7 26.71,25.9 | v34.21,23.4 33.14,23.4 33.14,24.37 32.81,24.7 32.81,25.5
  Bottom 2.184: X16.2 X16.1 | X17.1 26.86,29.76 25.91,30.7
  other vias: 10.81,27.1 18.31,27 21.71,23.1 15.81,21.2
  pour Bottom (isolate 0.406): 41.11,43.7 1.71,43.7 1.71,18.5 18.31,18.5 18.11,21.9 41.11,21.9
  pour Top (isolate 0.406): 41.11,43.7 1.71,43.7 1.71,18.5 18.91,18.5 18.91,18.2 19.61,18.2 19.61,21.9 41.11,21.9
GND_PI1
  Bottom 1.93: GND1.MP 28.32,51.51 X15.2 26.99,51.73 23.81,54.9 18.71,54.9 15.54,58.08 X14.2
  Bottom 2.184: X14.2 X14.1 | X15.2 X15.1
  pour Bottom (isolate 0.406): 0.11,64.7 0.11,45.8 42.71,45.8 42.71,64.7
  pour Top (isolate 0.406): 0.11,64.7 0.11,45.8 42.71,45.8 42.71,64.7
GND_SB  (via drill 0.6)
  Top 0.406: v46.81,67 45.61,68.2 45.61,68.1 v44.51,67
  Top 1.676: X8.2 47.11,18.42
  Top 2.54: C23.- C26.- | C23.- C27.- 45.61,68.2 C28.- C29.- C30.- 45.61,24.4 47.14,22.88 X8.2 45.87,17.12 X8.1 | C23.- 47.21,98 53.49,104.28 X9.2 | X9.1 54.76,108.84 53.51,107.6
  other vias: 46.81,94.5 46.81,87.5 46.81,80.5 46.81,73.5 46.81,59.5 46.81,53 46.81,45 46.81,38.5 46.81,31.5 44.51,94.5 44.51,87.5 44.51,80.5 44.51,73.5 44.51,59.5 44.51,53 44.51,45 44.51,38.5 44.51,31.5
  pour Bottom (isolate 0.406): 40.11,120.7 60.61,120.7 60.61,5.2 40.11,5.2
  pour Bottom (no thermals): 44.21,19.8 48.81,19.8 48.81,13.5 44.21,13.5
  pour Bottom (no thermals): 56.11,111.6 56.11,106.2 52.31,106.2 52.31,111.6
GND_T  (via drill 0.6)
  Top 0.813: JP2T.1 96.74,118.49 PGNDT1.1
  Bottom 0.813: Q2.2 92.45,62.1 91.5,61.15 90.55,60.2 Q3.2 88.63,59.72 84.36,59.72 82.77,61.31 JP1T.1
  other vias: 95,77.02 99.28,63.21 97.54,68.29
  pour Bottom (isolate 0.305): 100.39,120.52 100.39,58.52 80.39,58.52 80.39,120.52
  pour Top (isolate 0.305): 100.39,120.52 100.39,58.52 80.39,58.52 80.39,120.52
GND_T1  (via drill 0.6)
  Top 0.813: JP2T1.1 118.44,118.49 PGNDT2.1
  Bottom 0.813: Q4.2 114.15,62.1 113.2,61.15 112.25,60.2 Q5.2 110.33,59.72 106.06,59.72 104.47,61.31 JP1T1.1
  other vias: 116.7,77.02 120.98,63.21 119.24,68.29
  pour Bottom (isolate 0.305): 122.09,120.52 122.09,58.52 102.09,58.52 102.09,120.52
  pour Top (isolate 0.305): 122.09,120.52 122.09,58.52 102.09,58.52 102.09,120.52
GND_T2  (via drill 0.4)
  Top 0.305: IC21.5 140.48,110.61 141.34,110.61 | IC24.5 140.59,101.4 141.34,101.4 | IC23.5 140.55,92.03 141.34,92.03 | IC22.5 140.48,82.67 141.34,82.67 | IC25.5 140.59,73.46 141.34,73.46 | JP1T2.1 124.52,61.56 125.63,60.44 127.2,60.44 R24.2 R22.2 R19.2 R18.2 R79.2
  Top 0.61: JP2T2.1 140.93,114.35 141.34,113.94 141.34,110.61 141.34,104.28 R65.1 141.34,103.92 141.34,101.4 141.34,95.04 R74.1 141.34,94.75 141.34,92.03 141.34,85.67 R71.1 141.34,85.38 141.34,82.67 141.34,76.46 R68.1 141.34,76.17 141.34,73.46 141.34,67.09 R77.1
  Top 1.016: JP2T2.1 138.49,116.17 v137.85,116.8 PGNDT3.1
  Top 1.27: C16.2 135.28,112.04 133.41,112.04 | 135.79,74.73 C74.2 135.76,74.41 133.41,74.41 | C24.2 135.66,102.04 133.09,102.04 | C21.2 135.66,92.83 133.09,92.83 | 133.09,83.62 135.76,83.62 C19.2
  Bottom 1.27: JP2T2.1 138.49,112.99 137.53,112.04 130.41,112.04 D14.A 129.12,108.41 129.12,105.37 R64.1 129.88,102.85 D17.A 129.12,99.41 129.12,96.21 R73.1 129.88,94.01 D16.A 128.96,90.72 128.96,87.68 R70.1 129.88,84.69 128.02,82.84 | JP1T2.1 124.52,65.2 | R76.1 129.12,69.85 129.12,73.21 D18.A 129.88,76.33 R67.1 129.12,78.7 129.12,81.74 128.02,82.84 | 128.02,82.84 D15.A
  other vias: 123.72,114.42 123.41,59.81 124.83,61.55 139.44,61.71 133.72,112.04 131.34,112.04 126.1,112.19 130.07,112.04 130.07,110.45 133.57,107.27 128.8,106.8 130.07,108.86 128.8,112.04 127.53,112.04 126.26,102.67 129.28,102.67 130.39,102.67 131.5,102.67 131.5,103.62 129.91,101.56 129.91,100.29 133.33,97.91 128.64,98.54 128.64,97.11 126.1,93.78 129.28,93.78 130.23,93.78 131.18,93.94 131.58,94.81 129.91,92.67 129.91,91.56 128.49,89.97 128.49,88.54 133.25,89.02 126.82,85.05 125.87,85.05 129.52,85.05 130.47,85.05 131.42,85.37 129.83,84.1 129.83,83.14 129.83,82.19 128.72,81.08 128.72,79.65 133.33,80.13 126.82,76.32 125.87,75.68 129.68,76.32 131.5,76.32 130.55,76.32 130.07,75.36 130.07,74.41 130.07,73.46 129.76,72.35 128.49,72.35 129.12,71.55 129.12,70.6 133.25,71.4 126.42,67.43 125.47,62.35
  pour Bottom (isolate 0.305, rank 2): 142.14,120.45 142.14,58.45 122.14,58.45 122.14,120.45
  pour Top (isolate 0.305, rank 2): 142.14,120.45 142.14,58.45 122.14,58.45 122.14,120.45
  pour Bottom (no thermals): 125.63,65.68 125.63,62.51 123.25,62.51 123.25,65.68
  pour Top (no thermals): 138.8,120.93 138.8,116.64 136.74,116.64 136.74,120.93
  pour Top (no thermals): 139.6,116.01 139.6,113.15 137.38,113.15 137.38,116.01
  pour Bottom (no thermals): 139.28,115.69 139.28,113.15 137.38,113.15 137.38,115.69
  pour Bottom (no thermals): 138.8,120.93 138.8,116.64 136.74,116.64 136.74,120.93
GND_USB1  (via drill 0.4)
  Top 0.305: 10.19,10.43 10.84,9.78 IC19.21 14.24,9.78 | 9.79,7.83 IC19.18 | IC19.25 10.69,12.38 10.51,12.2 | IC19.26 10.51,13.03 10.51,13
  Top 0.406: OK5.5 23.03,17.2 | X18.GND 36.31,12.2 v37.11,12.2 v37.11,14 36.31,13.2 36.01,13.2 36.11,13.3 | 9.21,10.43 10.19,10.43 10.51,10.75 10.51,12.2 | 9.21,10.43 IC19.7 | 9.79,7.83 9.21,8.4 9.21,10.43 | 14.24,9.78 C68.2 C67.2 17.51,9.7 v17.91,10.1
  Top 0.813: C66.2 24.31,7.4 v24.01,7.1 22.71,7.1 C69.-
  other vias: 22.21,15.5 21.71,8.6 36.41,7.5 9.61,13.3 6.11,9.1 9.61,6.3 38.41,15 30.41,9.2 36.41,6
  pour Bottom (isolate 0.406): 2.21,4.1 40.81,4.1 40.81,18.6 20.91,18.6 20.91,15.9 2.21,15.9
  pour Top (isolate 0.406): 2.21,4.1 40.81,4.1 40.81,18.6 20.91,18.6 20.91,15.9 2.21,15.9
LED_B  (via drill 0.6)
  Top 0.305: 70.56,93.69 70.56,93.8 JP1.4 | D3.1 65.64,90.67 67.38,92.42 69.69,92.42 70.33,93.05
  Top 0.406: IC5.9 74.61,78.75 v74.61,80.99 | 70.33,92.82 70.24,92.73 | 70.33,92.82 70.33,93.05 JP1.4 | v74.13,90.99 73.58,91.54 73.58,92.26 73.1,92.73 70.41,92.73 70.33,92.82
  Bottom 0.406: v74.13,90.99 74.69,90.51 74.69,88.93 74.85,88.77 74.85,81.23 v74.61,80.99
LED_G  (via drill 0.6)
  Top 0.305: D4.1 67.86,88 67.86,88.45 68.1,88.69 70.16,88.69 71.51,90.04 74.69,90.04 75.08,90.35 75.08,91.94 74.21,91.94 74.21,96.26 arc-90 74.53,96.58
  Top 0.406: IC5.2 75.89,71.37 76.59,70.67 v76.59,69.95 | JP1.3 74.53,96.58 76.08,96.58 76.59,96.07 76.59,93.77 v76.67,93.69
  Bottom 0.406: v76.67,93.69 76.67,93.13 78.02,91.78 78.02,86.54 76.43,84.96 76.43,82.26 76.91,81.78 76.91,70.27 v76.59,69.95
LED_R  (via drill 0.6)
  Top 0.305: D5.1 70.11,87.84 71.04,88.69 71.75,89.4 v75.72,89.4
  Top 0.406: JP1.2 75.41,92.66 75.32,92.58 75.72,92.58 v75.72,89.4 | IC5.1 75.16,70.57 v75.16,69.18
  Bottom 0.406: v75.72,89.4 arc90 75.64,89.32 75.64,70.5 75.61,69.82 v75.16,69.18
LED_U  (via drill 0.6)
  Top 0.305: D9.1 62.28,88.69 63.89,88.69 64.13,88.93 64.13,92.92 JP1.6 67.34,94.04 v67.46,94.16
  Top 0.406: IC5.11 71.92,82.49 71.75,82.65 v68.65,82.65
  Bottom 0.406: v67.46,94.16 67.23,93.93 67.23,84.08 v68.65,82.65
LED_W
  Top 0.406: JP1.5 67.79,96.63 | 65.56,91.47 | JP1.5 67.86,96.5 | 65.56,91.47 64.76,90.67 64.76,88.69 64.05,87.97 63.71,87.97 D8.1 63.57,86.94 74.69,86.94 74.69,83.29 74.29,82.89 73.1,82.89 72.72,82.51 IC5.10 | 65.56,91.47 67.15,93.05 68.5,93.05 69.05,93.53 69.05,94.72 67.79,95.99 JP1.5
MISO  (via drill 0.4)
  Top 0.305: v175.01,92 175.71,92.7 IC1.16
  Bottom 0.305: v175.01,92 175.01,93.45 173.27,95.2 172.71,95.2 170.66,97.26 ISP.1
MISO1  (via drill 0.4)
  Top 0.305: JP3B.1 | JP3B.1 62.3,52.1 PB4.1 | IC5.16 67.06,77.66 65.16,79.56 64.53,79.56 v64.21,79.24 | 67.7,25.58 67.54,25.74 67.54,27.01 66.43,27.01 65.32,28.12 65.32,30.03 64.92,30.43 v64.84,30.43 | JP3B.1 64.21,52.1 v64.21,49.95
  Top 0.406: JP3A.1 67.7,25.58 67.86,25.43
  Bottom 0.305: v64.21,79.24 63.57,78.45 63.57,49.87 | 63.57,49.87 63.57,31.93 64.84,30.66 v64.84,30.43 | v64.21,49.95 63.65,49.95 arc90 63.57,49.87
MISO2  (via drill 0.4)
  Top 0.305: v20.11,100.6 20.81,99.91 IC15.16
  Bottom 0.305: v20.11,100.6 21.56,100.6 23.31,102.35 23.31,103.8 24.47,104.96 ISP1.1
MISO3
  Top 0.305: ISP2.1 139.53,7.35 134.71,7.35 134.11,7.9 134.11,9.3 134.51,9.7 IC32.16
MOSI
  Top 0.305: IC1.15 178.01,91.9 178.21,92.1 178.21,98.7 176.61,100.3 174.45,100.3 ISP.4
MOSI1  (via drill 0.4)
  Top 0.305: JP3B.4 66.75,57.18 66.75,55.11 66.27,54.64 v65.08,54.64 65.24,54.64 62.3,54.64 PB3.1 | IC5.15 68.72,78.54 68.34,78.92 66.59,78.92 65.16,80.35 v64.21,80.35 | JP3A.4 70.4,29.55 69.29,28.44 67.07,28.44 66.59,28.92 66.59,31.54 v65.08,33.05
  Bottom 0.305: v64.21,80.35 64.37,80.35 66.11,78.61 66.11,76.86 65.48,76.23 65.48,71.3 66.11,70.67 66.11,60.35 64.92,59.16 64.92,54.64 | 64.92,54.64 v65.08,54.64 | 64.92,54.64 | v65.08,33.05 64.84,33.28 64.84,46.38 65.48,46.7 65.48,48.21 65.96,48.84 65.96,50.51 64.92,51.54 64.92,54.64
MOSI2  (via drill 0.4)
  Top 0.305: v20.01,97.1 20.01,97.91 IC15.15
  Bottom 0.305: ISP1.4 28.95,101.1 26.81,101.1 24.81,99.1 24.01,99.1 22.01,97.1 v20.01,97.1
MOSI3
  Top 0.305: IC32.15 133.76,10.05 133.31,9.6 133.31,6.1 134.61,4.8 136.71,4.8 137.99,5.83 ISP2.4
N$1
  Top 0.406: IC3.3 148.56,106.98 R6.2
  Top 1.016: W-.MP C7.1
  Top 1.27: W-.MP 148.09,107.3 R6.2
N$2
  Top 1.016: C7.2 W+.MP
  Top 1.27: W+.MP 147.87,114.55 L1.P$2
N$3
  Top 0.406: IC3.1 152.24,108.28 D2.C
  Top 1.27: D2.C 151.51,111.8 L1.P$1 156.61,114.6 Q7.3
N$4
  Top 0.406: 148.36,58.18 R9.2 148.63,57.9 153.61,57.9 154.01,58.3 154.01,59.5 154.19,59.68 IC6.3
  Top 1.016: R-.MP C9.1
  Top 1.27: R9.2 148.03,58.5 R-.MP
N$5
  Top 0.406: R7.2 IC3.4
N$6
  Top 1.016: C9.2 R+.MP
  Top 1.27: R+.MP L2.P$2
N$7
  Top 0.406: IC3.8 159.99,108.28 R8.1
N$8
  Top 0.406: IC6.1 152.24,60.98 D1.C
  Top 1.27: D1.C 151.81,63.1 L2.P$1 Q8.3
N$9
  Top 0.406: R10.2 IC6.4
N$10
  Top 0.406: IC3.6 157.84,106.98 157.11,107.7 157.11,109.8 156.06,110.85 Q7.1
N$11
  Top 0.406: IC6.8 161.09,60.98 R11.1
N$12
  Top 0.406: IC6.6 158.54,59.68 157.11,61.1 157.11,61.3 156.36,62.05 Q8.1
N$13
  Top 0.406: IC7.3 148.66,74.48 R12.2
  Top 1.016: G-.MP C11.1
  Top 1.27: R12.2 148.03,74.6 G-.MP
N$14
  Top 1.016: C11.2 G+.MP
  Top 1.27: L8.P$2 148.01,82.1 G+.MP
N$15
  Top 0.406: IC7.1 152.64,75.78 D12.C
  Top 1.27: D12.C 152.11,79.6 L8.P$1 Q9.3
N$16
  Top 0.406: R13.2 IC7.4
N$17
  Top 0.406: IC7.8 161.69,75.78 R14.1
N$18
  Bottom 0.406: X1.7 167.72,108.31 162.91,103.5 162.91,63.1 165.21,60.8 171.79,60.8 X2.7
N$19  (via drill 0.4)
  Top 0.406: v171.31,62.4 175.91,62.4 177.21,63.7 177.21,66.06 X2.8
  Bottom 0.406: X1.8 163.91,102.07 163.91,63.7 165.91,61.7 169.41,61.7 170.11,62.4 v171.31,62.4
N$20
  Top 0.406: IC7.6 158.74,74.48 157.41,75.8 157.41,76.9 156.36,77.95 Q9.1
N$21
  Top 0.406: IC8.3 148.86,91.08 R15.2
  Top 1.016: B-.MP C15.1
  Top 1.27: B-.MP 145.09,91.12 R15.2
N$22
  Top 1.016: C15.2 B+.MP
  Top 1.27: B+.MP 145.11,98.6 L9.P$2
N$23
  Top 0.406: IC8.1 152.54,92.38 D13.C
  Top 1.27: D13.C 151.91,96.1 L9.P$1 154.51,98.5 Q10.3
N$24
  Top 0.406: R16.2 154.91,90.23 IC8.4
N$25
  Top 0.406: IC8.8 161.49,92.38 R17.1
N$26
  Top 0.406: IC8.6 158.44,91.08 157.11,92.4 157.11,93.6 156.06,94.65 Q10.1
N$27
  Bottom 1.93: 171.41,66.8 172.71,64.2
N$28
  Bottom 1.93: 171.41,108.4 172.71,105.8
N$29  (via drill 0.4)
  Top 0.254: 134.04,105.37 137.85,105.37
  Top 0.305: 137.85,105.37 137.85,106.8 139.76,106.8 139.76,105.83 IC21.3 | 134.04,105.37 132.3,107.12 132.3,107.27 131.51,108.06 130.38,108.06 129.72,107.4 129.72,104.42 127.98,102.67 v127.69,102.67
  Top 1.27: C17.1 123.11,105.93 arc90 R-1.MP
  Bottom 0.305: v127.69,102.67 127.69,103.95 R64.2
  Bottom 1.27: R64.2 124.43,104.61 R-1.MP
N$30
  Top 1.27: R+1.MP 124.91,110.36 C17.2 126.28,106.79 L10.1
N$31
  Top 0.305: IC21.1 138.49,105.75 138.49,105.05 138.17,104.73 136.9,104.73 136.43,104.26 Q11.3
  Top 1.27: Q11.3 135.94,104.26 133.57,104.26 131.11,106.71 L10.2
  Bottom 1.27: D14.C 132.18,107.85 L10.2
N$32
  Top 0.305: 139.9,104.24 R65.2 140.43,104.66 IC21.4
N$33  (via drill 0.6)
  Top 0.406: v53.41,116.5 v47.31,116.5
  Bottom 0.406: X8.8 58.81,22.45 58.81,111.6 56.81,113.6 55.41,113.6 53.41,115.6 v53.41,116.5 | X9.8 45.87,114.36 46.81,115.3 46.81,116 v47.31,116.5
N$34  (via drill 0.6)
  Top 0.406: v51.71,115.2 v47.81,115.2
  Bottom 0.406: X8.7 53.49,20.88 56.41,23.8 56.41,111.8 56.01,112.2 53.11,112.2 51.71,113.6 v51.71,115.2 | X9.7 47.14,114.53 v47.81,115.2
N$35
  Top 0.305: IC21.8 138.48,111.71 R66.1
N$36
  Top 0.305: 78.66,65.83 78.66,66.52 IC9.1 78.81,64.8 77.86,63.84 75.8,63.84 71.92,67.72 IC5.30
N$37
  Top 0.305: 136.9,106.8 Q11.1 136.9,106.64 137.69,107.43 139.76,107.43 139.76,110.62 IC21.6
N$38
  Top 0.406: IC5.8 76.17,76.17 76.59,75.75 C18.2 77.39,75.96 X10.2
N$39
  Top 0.406: IC5.7 75.86,75.37 76.43,74.8 76.43,74.32 76.75,74 C31.2 | C31.2 | X10.1 77.39,87.18 78.81,85.91 78.81,76.86 78.5,76.7 78.5,74.64 77.86,74 C31.2 | C31.2
N$40
  Top 0.305: ADC6.1 62.15,76.54 62.15,75.75 63.57,75.75 64.76,74.57 IC5.19
N$41
  Top 0.305: 62.3,72.1 ADC7.1 62.15,72.17 65.23,72.17 IC5.22
N$42  (via drill 0.4, 0.4 pad 0.4)
  Top 0.305: L3.2 v64.45,70.27 | IC5.18 66.36,75.43 64.84,75.43 64.21,76.07 64.21,77.02 | 64.21,77.02 64.21,77.34 v64.45,77.57 | C35.2 64.13,77.1 64.21,77.02
  Bottom 0.305: v64.45,77.57 64.21,77.34 64.21,70.51 v64.45,70.27
N$43
  Top 0.305: IC5.20 64.6,73.77 63.73,74.64 C36.2
N$44  (via drill 0.4)
  Top 0.254: 134.04,77.42 137.85,77.42
  Top 0.305: IC22.3 139.78,78.86 137.85,78.86 137.85,77.42 | 134.04,77.42 132.3,79.17 132.3,80.6 131.57,81.33 130.07,81.33 129.72,80.98 129.72,77.75 128.29,76.32 v128.01,76.32
  Top 1.27: C20.1 123.11,78.02 W-1.MP
  Bottom 0.305: v128.01,76.32 128.01,76.97 R67.2
  Bottom 1.27: R67.2 124.83,77.94 W-1.MP
N$45
  Top 0.305: SJ1.2 73.58,86.04 D7.2
N$46
  Top 0.305: SJ2.2 71.59,86.04 D6.2
N$47
  Top 0.305: SJ3.2 D5.2 | D5.2
N$48
  Top 0.406: SJ4.2 D4.2
N$49
  Top 0.406: R26.1 71.86,54.05 SJ8.2 71.86,50.56 R25.2
N$50
  Top 0.305: SJ5.2 D3.2
N$51
  Top 0.305: SJ6.2 63.57,84.85 D8.2
N$52
  Top 0.406: D9.2 61.67,84.93 SJ7.2
N$53
  Top 0.406: R27.1 71.7,59.42 SJ9.2 71.7,55.85 R26.2
N$54
  Top 0.305: R29.2 68.36,64 69.92,64 70.32,64.4 IC5.28
N$55  (via drill 0.4)
  Top 0.305: 62.46,62.41 PB2.1 63.89,62.1 64.37,62.57 64.37,64.32 66.11,66.06 66.11,67.02 66.99,67.02 v66.99,68.29 | IC5.14 69.52,76.93 68.26,75.67 v68.26,74.4
  Bottom 0.305: v66.99,68.29 67.38,68.29 68.81,69.72 68.81,72.89 68.26,73.45 v68.26,74.4
N$56  (via drill 0.4)
  Top 0.305: XR.7 67.15,105.68 67.86,106.39 v68.18,106.39 68.5,106.71 71.35,106.71 71.99,107.34 76.91,107.34 77.86,108.29 v77.86,108.77 | 75.8,118.29 C.1 75.8,118.21 v76.91,117.1 | v69.92,43.36 69.92,42.89 70.56,42.25 73.26,42.25 73.5,42.01 XL.7 73.5,35.18 73.89,34.79 77.54,34.79 v77.54,34.63 | C_L.1 75.8,23.36 v76.59,24.16
  Bottom 0.305: v68.18,106.39 67.78,105.99 67.78,96.47 69.13,95.12 69.13,93.21 68.5,92.58 68.5,85.27 70.24,83.53 70.24,81.31 70.56,80.99 70.56,77.02 71.35,76.23 71.35,68.29 70.4,67.34 70.4,64.95 72.07,63.29 72.07,61.78 70.88,60.59 70.88,59.24 69.77,58.13 69.77,53.05 71.19,51.62 71.19,44.16 70.4,43.36 v69.92,43.36 | v77.86,108.77 78.18,109.09 78.18,115.59 76.91,116.87 v76.91,117.1 | 76.59,24.63 78.1,26.06 78.1,31.3 77.54,31.85 77.54,33.52 v77.54,34.63
  Bottom 0.406: v76.59,24.16 76.59,24.63
N$57  (via drill 0.4)
  Top 0.305: XR.8 65.88,106.47 66.59,107.18 v67.38,107.18 67.54,107.34 71.19,107.34 71.83,107.98 75.96,107.98 76.75,108.77 76.75,109.32 v77.31,109.88 | XL.8 74.69,38.65 | v70.32,47.33 72.31,47.33 72.54,47.02 72.54,44.32 74.77,42.09 XL.8 | D_L.1 74.05,23.04 v75.16,24.16 | v77.54,36.22 77.2,36.22 XL.8 | D.1 74.37,118.77 74.37,117.66 74.92,117.1 v75.64,117.1
  Bottom 0.305: v67.38,107.18 67.15,107.02 67.15,95.35 67.86,95.35 68.42,94.8 68.42,93.45 67.86,92.89 67.86,84.96 69.61,83.21 69.61,80.99 69.92,80.67 69.92,76.7 70.72,75.91 70.72,68.45 69.77,67.49 69.77,64.72 71.43,63.05 71.43,62.02 70.24,60.83 70.24,59.4 69.13,58.29 69.13,52.89 70.56,51.46 70.56,47.57 v70.32,47.33 | v77.31,109.88 77.54,110.12 77.54,115.28 75.72,117.1 v75.64,117.1 | v75.16,24.16 75.16,24.47 77.39,26.7 77.39,31.14 76.67,31.86 76.67,35.59 77.31,36.22 v77.54,36.22
N$58
  Top 0.813: R_W.2 81.82,61.31 81.34,61.78 81.34,72.13 W5.K@1 W5A.K
N$59
  Top 0.305: 69.52,69.31 IC5.27 69.52,65.09 arc90 R28.2
N$60
  Top 0.813: U1A.K U1.P$1 99.09,102.29 99.44,102.1 99.44,93.92 U2A.A U2.P$2
N$61
  Top 0.813: G2.A 91.5,97.04 91.5,105.44 87.99,108.95 G1.K
N$62
  Bottom 0.813: G2.K 88.53,93.13 G3.A
N$63
  Top 0.813: G4.A 91.34,78.21 91.34,82.74 90.23,83.85 90.23,88.29 88.56,89.96 G3.K
N$64
  Bottom 0.813: G4.K 88.53,74.14 G5.A
N$65
  Top 0.61: 89.12,63.53 89.12,66.23
  Top 0.813: 89.12,66.23 89.12,70.35 88.5,70.97 G5.K | 89.12,63.53 89.12,60.41 R_G.2
N$66
  Bottom 0.813: B1.K 88.53,105.79 B2.A
N$67
  Top 0.813: B3.A 91.5,90.71 91.5,95.28 90.39,96.39 90.39,100.83 88.6,102.62 B2.K
N$68
  Bottom 0.813: B3.K 88.53,86.8 B4.A
N$69
  Top 0.813: B5.A 91.19,72.04 91.19,76.39 89.92,77.66 89.92,82.1 88.38,83.63 B4.K
N$70
  Top 0.61: 92.77,62.73 92.3,62.73 91.66,63.53 91.66,66.59
  Top 0.813: B5.K 91.88,66.8 91.66,66.59 | R_B.2 93.2,62.31 92.77,62.73
N$71
  Top 0.61: 87.06,110.2 88.65,110.2
  Top 0.813: RD2.A 96.57,110.2 88.65,110.2 | 87.06,110.2 84.52,107.98 84.52,107.34 84.48,107.34 RD1.K
N$72
  Top 0.813: RD2.K 94.84,105.93 94.84,103.95 RD3.A
N$73
  Bottom 0.813: RD3.K 88.53,99.46 RD4.A
N$74
  Top 0.813: RD5.A 91.5,84.38 91.5,89.09 90.23,90.36 90.23,94.64 88.58,96.29 RD4.K
N$75
  Bottom 0.813: RD5.K 88.53,80.47 RD6.A
N$76  (via drill 0.6)
  Top 0.813: v84.36,62.73 84.36,61.01 R_W.1
  Bottom 0.813: Q3.3 85.95,61.15 v84.36,62.73
N$77
  Bottom 0.406: Q2.1 93.42,59.88 95.15,59.88 96.11,59.88 96.27,60.04 96.58,60.35 96.58,61.15 96.58,63.37 95.47,64.48 JP1T.6
N$78
  Top 0.813: JP1T.5 92.93,65.59
  Bottom 0.406: JP1T.5 92.93,64.48 91.5,63.05 90.55,62.1 Q3.1
N$79
  Top 0.813: JP1T.3 87.85,64.48 86.58,63.21 86.58,61.15 R_G.1
N$80
  Top 0.813: JP1T.4 90.39,61.36 R_B.1
N$81
  Bottom 0.813: JP1T.2 85.31,65.42 RD8.K
N$82
  Top 0.813: R_R.1 81.82,109.43 RD1.A
N$83
  Bottom 0.61: 91.98,75.43 93.88,75.43
  Bottom 0.813: RD6.K 89.77,75.43 91.98,75.43 | 93.88,75.43 95.94,75.43 RD7.A
N$84
  Bottom 0.61: 86.9,72.26 88.65,72.26
  Bottom 0.813: RD7.K 96.57,72.26 88.65,72.26 | 86.9,72.26 84.83,72.26 RD8.A
N$85
  Top 0.305: W5A.A W5.A@2
  Top 0.813: W5A.A 83.7,76.68 84.3,77.22 85.31,78.13 85.31,85.52 W4A.K W4.K@1
N$86
  Top 0.813: W3.K@1 W3A.K 85.63,97.54 85.63,90.93 W4A.A W4.A@2
N$87
  Top 0.813: W3A.A W3.A@2 | W2A.K W2.K@1
  Bottom 0.61: 92.14,100.75 93.57,100.75
  Bottom 0.813: W3A.A 85.26,102 86.5,100.75 92.14,100.75 | 93.57,100.75 94.84,100.75 95.15,100.36 95.15,99 W2A.K
N$88
  Top 0.813: W1.K@1 W1A.K 95.79,85.7 95.79,97.5 97.12,98.83 W2A.A W2.A@2
N$89
  Top 0.61: 96.74,66.39 96.74,63.53 97.38,62.89
  Top 0.813: 96.74,66.39 95.47,67.66 95.47,74.58 U5.P$1 U5A.K | 98.49,61.31 98.81,61.31 R_U.2 98.96,61.31 97.38,62.89
N$90
  Top 0.406: U5A.A U5.P$2
  Top 0.813: U4A.K U4.P$1
  Bottom 0.61: 87.22,78.61 88.8,78.61
  Bottom 0.813: U5A.A 96.79,78.61 88.8,78.61 | 87.22,78.61 84.94,78.61 83.08,80.47 U4A.K
N$91
  Top 0.813: U3A.K U3.P$1 | U4A.A U4.P$2
  Bottom 0.813: U4A.A 83.99,83.01 84.68,83.69 84.68,91.37 U3A.K
N$92
  Top 0.813: U3.P$2 U3A.A | U2A.K U2.P$1
  Bottom 0.61: 91.9,94.4 | 91.9,94.4 93.57,94.4
  Bottom 0.813: U3A.A 86.03,95.67 87.38,94.4 91.9,94.4 | 93.57,94.4 94.44,94.4 95.79,93.06 95.79,91.79 U2A.K
N$93  (via drill 0.6)
  Top 0.813: R_U.1 95.77,61.8 v95,62.58
  Bottom 0.406: Q2.3 95.47,61.32
  Bottom 0.813: 95.47,61.32 95.47,62.1 v95,62.58
N$94
  Top 0.813: R_W1.2 103.52,61.31 103.04,61.78 103.04,72.13 W8.K@1 W5A1.K
N$95
  Top 0.813: U1A1.K U6.P$1 120.79,102.29 121.14,102.1 121.14,93.92 U2A1.A U7.P$2
N$96
  Top 0.813: G7.A 113.2,97.04 113.2,105.44 109.69,108.95 G6.K
N$97
  Bottom 0.813: G7.K 110.23,93.13 G8.A
N$98
  Top 0.813: G9.A 113.04,78.21 113.04,82.74 111.93,83.85 111.93,88.29 110.26,89.96 G8.K
N$99
  Bottom 0.813: G9.K 110.23,74.14 G10.A
N$100
  Top 0.61: 110.82,63.53 110.82,66.23
  Top 0.813: 110.82,66.23 110.82,70.35 110.2,70.97 G10.K | 110.82,63.53 110.82,60.41 R_G1.2
N$101
  Bottom 0.813: B6.K 110.23,105.79 B7.A
N$102
  Top 0.813: B8.A 113.2,90.71 113.2,95.28 112.09,96.39 112.09,100.83 110.3,102.62 B7.K
N$103
  Bottom 0.813: B8.K 110.23,86.8 B9.A
N$104
  Top 0.813: B10.A 112.89,72.04 112.89,76.39 111.62,77.66 111.62,82.1 110.08,83.63 B9.K
N$105
  Top 0.61: 114.47,62.73 114,62.73 113.36,63.53 113.36,66.59
  Top 0.813: B10.K 113.58,66.8 113.36,66.59 | R_B1.2 114.9,62.31 114.47,62.73
N$106
  Top 0.61: 108.76,110.2 110.35,110.2
  Top 0.813: RD10.A 118.27,110.2 110.35,110.2 | 108.76,110.2 106.22,107.98 106.22,107.34 106.18,107.34 RD9.K
N$107
  Top 0.813: RD10.K 116.54,105.93 116.54,103.95 RD11.A
N$108
  Bottom 0.813: RD11.K 110.23,99.46 RD12.A
N$109
  Top 0.813: RD13.A 113.2,84.38 113.2,89.09 111.93,90.36 111.93,94.64 110.28,96.29 RD12.K
N$110
  Bottom 0.813: RD13.K 110.23,80.47 RD14.A
N$111  (via drill 0.6)
  Top 0.813: v106.06,62.73 106.06,61.01 R_W1.1
  Bottom 0.813: Q5.3 107.65,61.15 v106.06,62.73
N$112
  Bottom 0.406: Q4.1 115.12,59.88 116.85,59.88 117.81,59.88 117.97,60.04 118.28,60.35 118.28,61.15 118.28,63.37 117.17,64.48 JP1T1.6
N$113
  Top 0.813: JP1T1.5 114.63,65.59
  Bottom 0.406: JP1T1.5 114.63,64.48 113.2,63.05 112.25,62.1 Q5.1
N$114
  Top 0.813: JP1T1.3 109.55,64.48 108.28,63.21 108.28,61.15 R_G1.1
N$115
  Top 0.813: JP1T1.4 112.09,61.36 R_B1.1
N$116
  Bottom 0.813: JP1T1.2 107.01,65.42 RD15.K
N$117
  Top 0.813: R_R1.1 103.52,109.43 RD9.A
N$118
  Bottom 0.61: 113.68,75.43 115.58,75.43
  Bottom 0.813: RD14.K 111.47,75.43 113.68,75.43 | 115.58,75.43 117.64,75.43 RD16.A
N$119
  Bottom 0.61: 108.6,72.26 110.35,72.26
  Bottom 0.813: RD16.K 118.27,72.26 110.35,72.26 | 108.6,72.26 106.53,72.26 RD15.A
N$120
  Top 0.305: W5A1.A W8.A@2
  Top 0.813: W5A1.A 105.4,76.68 106,77.22 107.01,78.13 107.01,85.52 W4A1.K W9.K@1
N$121
  Top 0.813: W10.K@1 W3A1.K 107.33,97.54 107.33,90.93 W4A1.A W9.A@2
N$122
  Top 0.813: W3A1.A W10.A@2 | W2A1.K W6.K@1
  Bottom 0.61: 113.84,100.75 115.27,100.75
  Bottom 0.813: W3A1.A 106.96,102 108.2,100.75 113.84,100.75 | 115.27,100.75 116.54,100.75 116.85,100.36 116.85,99 W2A1.K
N$123
  Top 0.813: W7.K@1 W1A1.K 117.49,85.7 117.49,97.5 118.82,98.83 W2A1.A W6.A@2
N$124
  Top 0.61: 118.44,66.39 118.44,63.53 119.08,62.89
  Top 0.813: 118.44,66.39 117.17,67.66 117.17,74.58 U8.P$1 U5A1.K | 120.19,61.31 120.51,61.31 R_U1.2 120.66,61.31 119.08,62.89
N$125
  Top 0.406: U5A1.A U8.P$2
  Top 0.813: U4A1.K U9.P$1
  Bottom 0.61: 108.92,78.61 110.5,78.61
